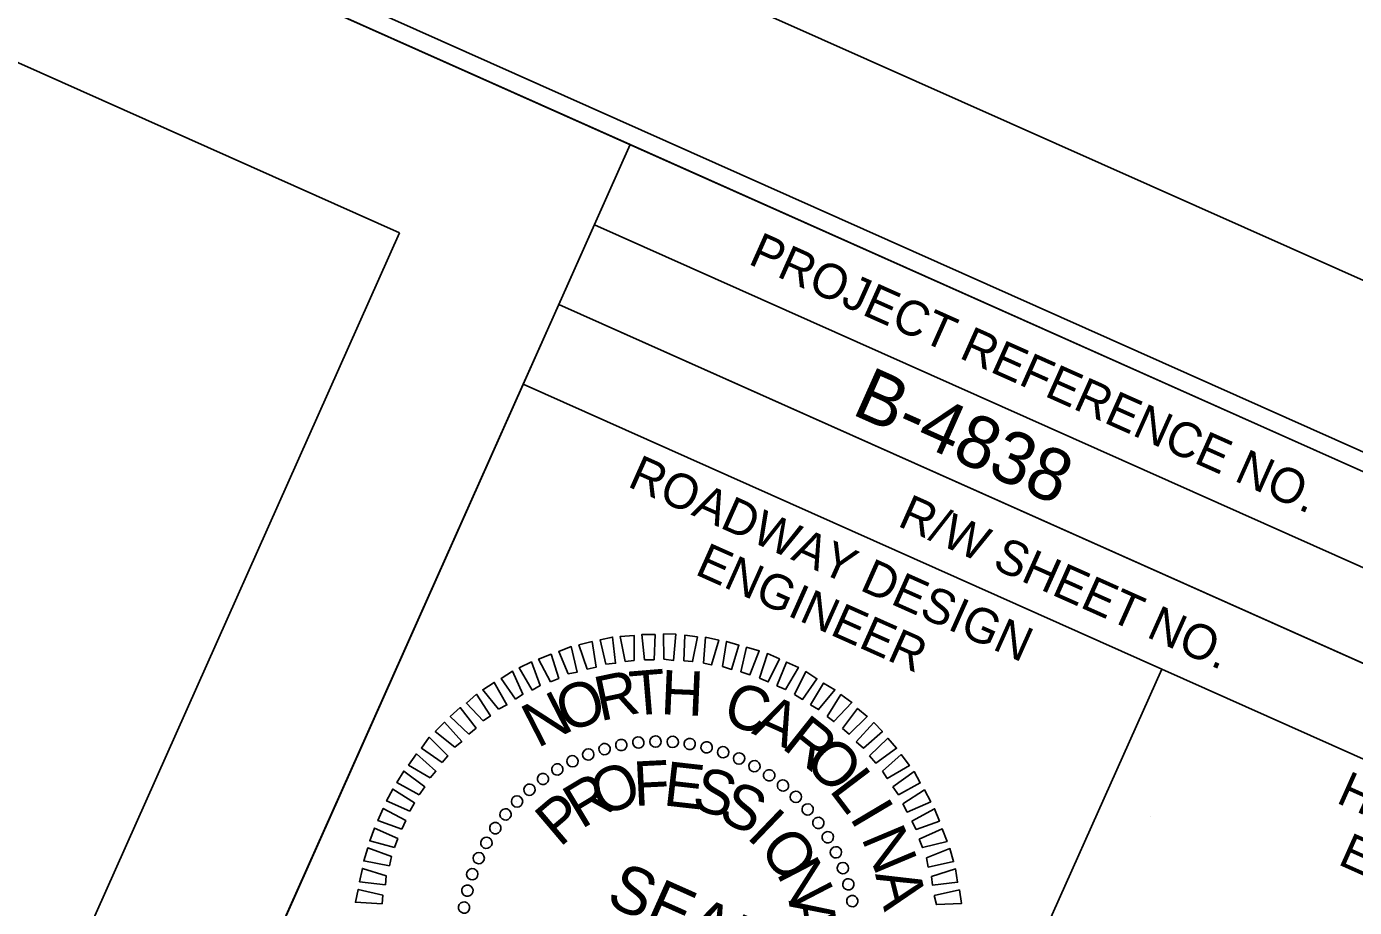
# Model space of a CAD drawing. Extents: x 2297991 to 2299183, y 599186 to 600200.
# Drawn here: x 2299005.9 to 2299120, y 599762.5 to 599838.1 of the extents above; entities that cross this region are included whole.
import ezdxf

# ---------------------------------------------------------------- set-up
doc = ezdxf.new("R2010")
doc.units = 0
for name, color, linetype in [('Default', 7, 'Continuous'), ('Exist DTM Drainline Cogo Comment', 7, 'Continuous'), ('Exist DTM Drainline Cogo Elevation', 7, 'Continuous'), ('Exist DTM Drainline Cogo Number', 7, 'Continuous'), ('Exist DTM Drainline Cogo Point CELL', 7, 'Continuous'), ('Exist Property Iron Pin Cogo Number', 7, 'Continuous'), ('Exist Roads EOP Cogo Comment', 7, 'Continuous'), ('Exist Roads EOP Cogo Point CELL', 7, 'Continuous'), ('Exist Roads EOP Other Cogo Number', 7, 'Continuous'), ('Exist Roads EOP Other Cogo Point CELL', 7, 'Continuous')]:
    doc.layers.add(name, color=color, linetype=linetype)

# ---------------------------------------------------------------- blocks, each defined once
blk = doc.blocks.new('POINT_DISPLAY')
at = {"layer": 'Default'}
blk.add_line((0, 0), (0, 0), dxfattribs=at)

msp = doc.modelspace()

# ---------------------------------------------------------------- linework, layer by layer
at = {"layer": 'Exist DTM Drainline Cogo Comment'}
msp.add_lwpolyline([(2298345.56, 600145.92), (2298088.78, 599570.64), (2298910.61, 599203.78), (2299118.52, 599669.59), (2299008.92, 599718.52), (2299057.79, 599827.99)], close=True, dxfattribs=at)
at = {"layer": 'Exist DTM Drainline Cogo Elevation'}
msp.add_lwpolyline([(2299182.82, 599788.6), (2298260.17, 600200.46), (2297991.14, 599597.77), (2298913.79, 599185.92)], close=True, dxfattribs=at)
at = {"layer": 'Exist DTM Drainline Cogo Number'}
msp.add_lwpolyline([(2299174.87, 599777.4), (2298261.8, 600184.98), (2298003.76, 599606.9), (2298916.82, 599199.32)], close=True, dxfattribs=at)
at = {"layer": 'Exist DTM Drainline Cogo Point CELL'}
for p, q in [((2299054.72, 599821.11), (2299164.32, 599772.18)), ((2299051.66, 599814.26), (2299048.6, 599807.41)), ((2299051.66, 599814.26), (2299161.27, 599765.33)), ((2299051.66, 599814.26), (2299161.27, 599765.33))]:
    msp.add_line(p, q, dxfattribs=at)
for points in [[(2299167.39, 599779.06), (2298345.56, 600145.92), (2298088.76, 599570.63), (2298910.59, 599203.77)], [(2299057.79, 599827.99), (2299167.39, 599779.06), (2299161.27, 599765.33), (2299051.66, 599814.26)], [(2299048.6, 599807.41), (2299103.42, 599782.94), (2299075.91, 599721.31), (2299021.09, 599745.77)], [(2299103.42, 599782.94), (2299158.21, 599758.49), (2299130.7, 599696.85), (2299075.91, 599721.31)]]:
    msp.add_lwpolyline(points, close=True, dxfattribs=at)
at = {"layer": 'Exist Property Iron Pin Cogo Number'}
msp.add_lwpolyline([(2298166.71, 599708.44), (2298114.07, 599590.51), (2298857.04, 599258.86), (2299012.14, 599726.11), (2298998.59, 599732.16), (2299037.98, 599820.4), (2298552.35, 600037.18)], close=True, dxfattribs=at)
at = {"layer": 'Exist Roads EOP Cogo Comment'}
msp.add_lwpolyline([(2298353.14, 600126.1), (2298108.59, 599578.22), (2298903.03, 599223.59), (2299108.19, 599683.24), (2298998.59, 599732.16), (2299037.98, 599820.4)], close=True, dxfattribs=at)
at = {"layer": 'Exist Roads EOP Other Cogo Number'}
msp.add_line((2299102.46, 599770.28), (2299102.46, 599770.28), dxfattribs=at)
at = {"layer": 'Exist Roads EOP Other Cogo Point CELL'}
for points in [[(2299055.68, 599783.37), (2299055.19, 599785.44), (2299056.27, 599785.69), (2299056.52, 599783.44)], [(2299057.36, 599783.58), (2299056.92, 599785.74), (2299058.11, 599785.83), (2299058.11, 599783.69)], [(2299059.01, 599783.73), (2299058.77, 599785.91), (2299059.92, 599785.91), (2299059.83, 599783.74)], [(2299060.67, 599783.8), (2299060.64, 599785.96), (2299061.7, 599785.93), (2299061.51, 599783.69)], [(2299062.39, 599783.66), (2299062.47, 599785.85), (2299063.55, 599785.7), (2299063.13, 599783.59)], [(2299064.06, 599783.44), (2299064.25, 599785.68), (2299065.39, 599785.43), (2299064.77, 599783.3)], [(2299052.45, 599782.52), (2299051.65, 599784.46), (2299052.72, 599784.87), (2299053.23, 599782.69)], [(2299054.08, 599782.94), (2299053.38, 599785.02), (2299054.5, 599785.3), (2299054.86, 599783.11)], [(2299065.7, 599783.15), (2299066.05, 599785.32), (2299067.12, 599784.99), (2299066.49, 599782.91)], [(2299067.28, 599782.7), (2299067.78, 599784.81), (2299068.86, 599784.51), (2299068.06, 599782.46)], [(2299068.89, 599782.17), (2299069.57, 599784.27), (2299070.59, 599783.81), (2299069.63, 599781.84)], [(2299049.35, 599781.13), (2299048.25, 599783.06), (2299049.29, 599783.56), (2299050.05, 599781.52)], [(2299050.94, 599781.86), (2299049.91, 599783.8), (2299050.98, 599784.21), (2299051.65, 599782.14)], [(2299070.37, 599781.51), (2299071.2, 599783.54), (2299072.22, 599783.08), (2299071.11, 599781.18)], [(2299047.93, 599780.36), (2299046.69, 599782.13), (2299047.68, 599782.76), (2299048.57, 599780.78)], [(2299071.88, 599780.76), (2299072.87, 599782.72), (2299073.82, 599782.11), (2299072.58, 599780.34)], [(2299046.48, 599779.49), (2299045.12, 599781.17), (2299046.1, 599781.8), (2299047.2, 599779.87)], [(2299073.27, 599779.88), (2299074.39, 599781.74), (2299075.36, 599781.17), (2299073.96, 599779.46)], [(2299045.15, 599778.5), (2299043.72, 599780.02), (2299044.58, 599780.78), (2299045.78, 599778.92)], [(2299074.7, 599778.87), (2299075.87, 599780.75), (2299076.82, 599780.07), (2299075.28, 599778.43)], [(2299043.93, 599777.34), (2299042.32, 599778.87), (2299043.18, 599779.64), (2299044.54, 599777.88)], [(2299076.01, 599777.84), (2299077.3, 599779.56), (2299078.13, 599778.86), (2299076.57, 599777.34)], [(2299042.72, 599776.22), (2299041.04, 599777.59), (2299041.84, 599778.38), (2299043.32, 599776.72)], [(2299077.17, 599776.7), (2299078.71, 599778.34), (2299079.44, 599777.57), (2299077.81, 599776.15)], [(2299041.63, 599774.93), (2299039.85, 599776.16), (2299040.52, 599777.09), (2299042.13, 599775.48)], [(2299078.33, 599775.48), (2299079.89, 599777), (2299080.65, 599776.14), (2299078.87, 599774.87)], [(2299040.6, 599773.61), (2299038.75, 599774.7), (2299039.44, 599775.65), (2299041.1, 599774.17)], [(2299079.44, 599774.17), (2299081.04, 599775.6), (2299081.76, 599774.65), (2299079.86, 599773.54)], [(2299039.65, 599772.15), (2299037.75, 599773.19), (2299038.34, 599774.18), (2299040.14, 599772.82)], [(2299080.32, 599772.82), (2299082.16, 599774.14), (2299082.69, 599773.16), (2299080.83, 599772.14)], [(2299038.87, 599770.73), (2299036.86, 599771.62), (2299037.39, 599772.64), (2299039.26, 599771.44)], [(2299081.18, 599771.36), (2299083.05, 599772.56), (2299083.59, 599771.54), (2299081.57, 599770.66)], [(2299038.18, 599769.19), (2299036.11, 599769.93), (2299036.57, 599770.97), (2299038.51, 599769.93)], [(2299081.96, 599769.87), (2299083.92, 599770.95), (2299084.33, 599769.88), (2299082.35, 599769.17)], [(2299037.55, 599767.62), (2299035.41, 599768.2), (2299035.82, 599769.28), (2299037.82, 599768.38)], [(2299082.6, 599768.32), (2299084.58, 599769.21), (2299084.99, 599768.14), (2299082.87, 599767.61)], [(2299037.11, 599766.04), (2299034.9, 599766.47), (2299035.24, 599767.58), (2299037.28, 599766.85)], [(2299083.21, 599766.72), (2299085.23, 599767.52), (2299085.55, 599766.41), (2299083.38, 599765.94)], [(2299036.76, 599764.42), (2299034.54, 599764.67), (2299034.79, 599765.82), (2299036.83, 599765.17)], [(2299083.64, 599765.12), (2299085.72, 599765.78), (2299085.9, 599764.63), (2299083.75, 599764.37)], [(2299036.47, 599762.78), (2299034.19, 599762.91), (2299034.43, 599764.02), (2299036.54, 599763.52)], [(2299083.88, 599763.5), (2299086.05, 599763.97), (2299086.24, 599762.82), (2299084.08, 599762.71)]]:
    msp.add_lwpolyline(points, close=True, dxfattribs=at)
for centre, major_axis in [((2299055.58, 599776.07), (-0.134, 0.467)), ((2299057.01, 599776.42), (-0.092, 0.477)), ((2299058.48, 599776.63), (-0.05, 0.483)), ((2299059.95, 599776.72), (-0.008, 0.486)), ((2299061.43, 599776.68), (0.034, 0.485)), ((2299062.89, 599776.51), (0.077, 0.48)), ((2299064.34, 599776.22), (0.118, 0.472)), ((2299065.76, 599775.8), (0.159, 0.459)), ((2299052.82, 599775.02), (-0.213, 0.437)), ((2299054.18, 599775.61), (-0.174, 0.454)), ((2299067.13, 599775.26), (0.198, 0.444)), ((2299068.45, 599774.6), (0.236, 0.425)), ((2299050.29, 599773.5), (-0.285, 0.394)), ((2299051.52, 599774.32), (-0.25, 0.417)), ((2299069.71, 599773.82), (0.272, 0.403)), ((2299049.13, 599772.58), (-0.319, 0.367)), ((2299070.9, 599772.94), (0.306, 0.377)), ((2299048.06, 599771.57), (-0.349, 0.338)), ((2299072, 599771.96), (0.338, 0.349)), ((2299047.08, 599770.46), (-0.377, 0.306)), ((2299073.02, 599770.89), (0.367, 0.319)), ((2299046.2, 599769.28), (-0.403, 0.272)), ((2299073.94, 599769.73), (0.394, 0.285)), ((2299045.43, 599768.02), (-0.425, 0.236)), ((2299074.75, 599768.5), (0.417, 0.25)), ((2299044.77, 599766.7), (-0.444, 0.198)), ((2299075.45, 599767.2), (0.437, 0.213)), ((2299076.04, 599765.85), (0.454, 0.174)), ((2299044.22, 599765.32), (-0.459, 0.159)), ((2299076.51, 599764.45), (0.467, 0.134)), ((2299043.8, 599763.91), (-0.472, 0.118)), ((2299043.51, 599762.46), (-0.48, 0.077)), ((2299076.85, 599763.01), (0.477, 0.092))]:
    msp.add_ellipse(centre, major_axis=major_axis, ratio=0.999708, dxfattribs=at)

# ---------------------------------------------------------------- block references
at = {"layer": 'Exist Roads EOP Other Cogo Point CELL', "xscale": 41.41195952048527, "yscale": 41.41195952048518, "rotation": -24.05480821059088}
for p in [(2299057.01, 599776.42), (2299058.48, 599776.65), (2299059.96, 599776.73), (2299061.42, 599776.7), (2299062.9, 599776.53), (2299054.17, 599775.61), (2299055.57, 599776.1), (2299064.35, 599776.21), (2299065.75, 599775.81), (2299067.14, 599775.26), (2299051.52, 599774.32), (2299052.81, 599775.04), (2299068.47, 599774.59), (2299050.28, 599773.51), (2299069.71, 599773.82), (2299070.91, 599772.95), (2299049.12, 599772.58), (2299072.03, 599771.97), (2299048.05, 599771.58), (2299073.03, 599770.9), (2299047.07, 599770.47), (2299073.95, 599769.74), (2299046.2, 599769.27), (2299074.76, 599768.49), (2299045.42, 599768.02), (2299075.48, 599767.21), (2299044.76, 599766.69), (2299044.21, 599765.31), (2299076.06, 599765.85), (2299043.81, 599763.9), (2299076.54, 599764.45), (2299076.86, 599763.01)]:
    msp.add_blockref('POINT_DISPLAY', p, dxfattribs=at)

# ---------------------------------------------------------------- texts
at = {"layer": 'Exist DTM Drainline Cogo Point CELL'}
for s, height, p in [('PROJECT REFERENCE NO.', 3.0001, (2299067.82, 599817.79)), ('ROADWAY DESIGN', 3.0001, (2299057.45, 599798.67)), ('R/W SHEET NO.', 3.0001, (2299080.64, 599795.28)), ('ENGINEER', 3, (2299063.24, 599791.12)), ('HYDRAULICS', 3, (2299118.32, 599771.5)), ('ENGINEER', 3, (2299118.46, 599766.21))]:
    msp.add_text(s, height=height, rotation=335.9448, dxfattribs=at).set_placement(p)
at = {"layer": 'Exist Roads EOP Cogo Point CELL'}
msp.add_text('B-4838', height=4.5, rotation=335.9448, dxfattribs=at).set_placement((2299076.69, 599804.88))
at = {"layer": 'Exist Roads EOP Other Cogo Point CELL'}
for s, height, rotation, p in [('R', 3.81, 11.9657, (2299055.19, 599778.45)), ('T', 3.81, 4.765, (2299057.87, 599778.92)), ('H', 3.81, 357.5647, (2299060.34, 599779.07)), ('N', 3.81, 27.1057, (2299049.81, 599776.12)), ('O', 3.81, 19.1669, (2299052.23, 599777.45)), ('C', 3.81, 343.1651, (2299065.59, 599778.32)), ('A', 3.81, 335.9655, (2299068.12, 599777.45)), ('R', 3.81, 321.5663, (2299070.68, 599776.23)), ('O', 3.81, 314.3664, (2299072.56, 599774.87)), ('F', 3.81, 2.9122, (2299058.14, 599771.18)), ('O', 3.81, 21.6264, (2299055.32, 599770.23)), ('E', 3.81, 353.5563, (2299060.54, 599771.25)), ('S', 3.81, 344.2008, (2299062.94, 599771)), ('L', 3.81, 307.1661, (2299074.8, 599772.54)), ('R', 3.81, 30.9848, (2299053.58, 599769.15)), ('S', 3.81, 334.8456, (2299065.19, 599770.07)), ('P', 3.81, 40.3441, (2299051.73, 599767.58)), ('I', 3.81, 300.7258, (2299076.56, 599770.21)), ('I', 3.81, 316.1348, (2299067.68, 599768.51)), ('N', 3.81, 292.7641, (2299077.59, 599768.45)), ('O', 3.81, 306.7787, (2299068.75, 599767.51)), ('SEAL', 4.05, 335.9452, (2299055.56, 599762.79)), ('N', 3.81, 297.4218, (2299070.29, 599765.42)), ('A', 3.81, 284.0073, (2299078.8, 599765.33)), ('A', 3.81, 278.7055, (2299071.38, 599763.05))]:
    msp.add_text(s, height=height, rotation=rotation, dxfattribs=at).set_placement(p)

doc.saveas('drawing.dxf')
